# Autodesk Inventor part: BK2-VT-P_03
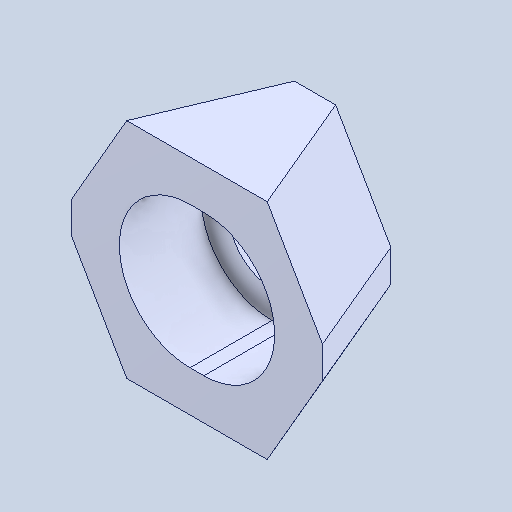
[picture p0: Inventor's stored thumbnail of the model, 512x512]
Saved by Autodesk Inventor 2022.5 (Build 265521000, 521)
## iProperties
Created: 2024-08
Part Number: BK2-VT-P_03
Material: 一般
Document SubType Name: Modeling
Designer: ImaoCorp
Density: 1 g/cm^3
Appearance: 既定
Author: ImaoCorp
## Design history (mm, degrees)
feature "BK2-VT-P_03"
node "ソリッド1"
